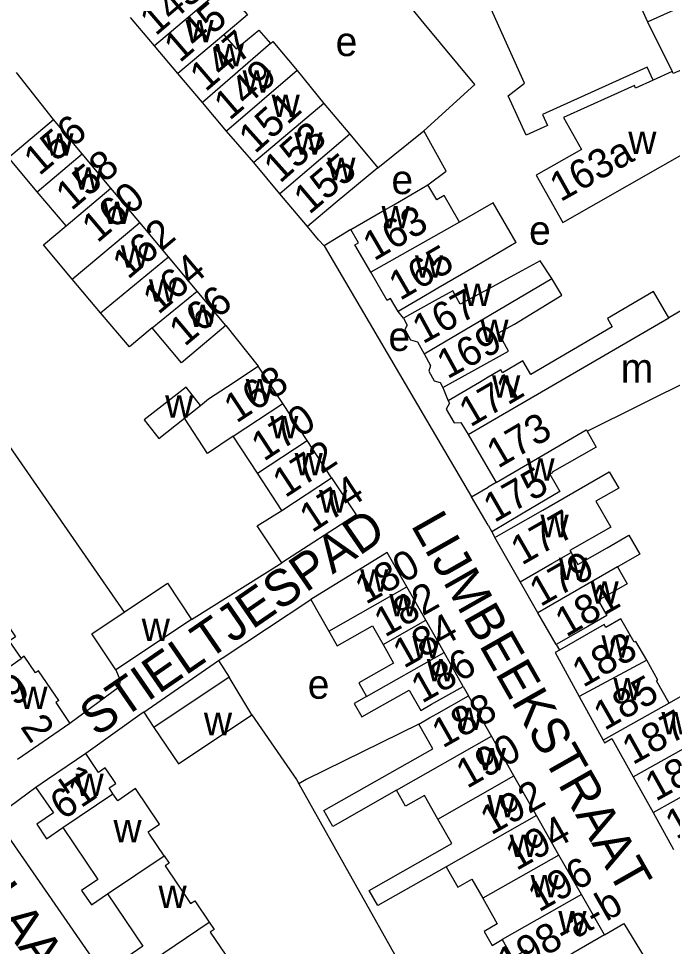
# Model space of a CAD drawing. Extents: x 159902 to 161769, y 383692 to 384875.
# Drawn here: x 160435.6 to 160525.3, y 384277.1 to 384404.5 of the extents above; entities that cross this region are included whole.
import ezdxf

# ---------------------------------------------------------------- set-up
doc = ezdxf.new("R2010")
doc.units = 0
for name, color, linetype in [('BLT_Basislijn', 7, 'Continuous'), ('BLT_Bebouwing', 7, 'Continuous'), ('BLT_Centroide', 7, 'Continuous'), ('BLT_Huisnummer', 7, 'Continuous'), ('BLT_Huisnummer_ tussenligend', 7, 'Continuous'), ('BLT_Huisnummer_reeks', 7, 'Continuous'), ('BLT_Onderverdeling_panden', 7, 'Continuous'), ('BLT_Straatnaam', 7, 'Continuous')]:
    doc.layers.add(name, color=color, linetype=linetype)

msp = doc.modelspace()

# ---------------------------------------------------------------- linework, layer by layer
at = {"layer": 'BLT_Basislijn'}
for p, q in [((160440.36, 384390.62), (160435.26, 384397.06)), ((160484.85, 384383.96), (160491.17, 384389.04)), ((160481.17, 384375.49), (160477.49, 384373.26)), ((160477.49, 384373.26), (160497.72, 384338.79)), ((160415.44, 384373.03), (160450.04, 384322.96)), ((160488.37, 384363.35), (160487.64, 384364.26)), ((160464.02, 384362.35), (160468.46, 384356.74)), ((160493.79, 384353.84), (160494.5, 384351.99)), ((160500.52, 384334.03), (160500.92, 384333.22)), ((160459.31, 384321.98), (160471.68, 384329.73)), ((160452.74, 384309.26), (160463.01, 384316.34)), ((160463.01, 384316.34), (160464.49, 384314.07)), ((160496.59, 384312.79), (160497.31, 384311.49)), ((160452.74, 384309.26), (160454.15, 384307.16))]:
    msp.add_line(p, q, dxfattribs=at)
for points in [[(160491.25, 384403.78), (160481.76, 384415.42), (160480.46, 384416.68), (160479.73, 384417.05), (160473.36, 384417.19), (160471.38, 384418.38), (160465.25, 384423.15), (160460.59, 384427.48)], [(160491.17, 384389.04), (160498.17, 384395.4), (160491.25, 384403.78)], [(160491.75, 384381.65), (160494.27, 384383.51), (160491.17, 384389.04)], [(160477.49, 384373.26), (160476.74, 384374.11), (160475.22, 384375.91)], [(160463.01, 384316.34), (160463.52, 384316.68), (160475.68, 384324.74)], [(160448.92, 384315.05), (160449.48, 384313.73), (160449.41, 384312.71), (160442.62, 384307.71)], [(160452.74, 384309.26), (160452.54, 384309.12), (160444.8, 384303.56)], [(160467.58, 384308.87), (160473.72, 384300), (160474.04, 384299.43)], [(160490.49, 384307.61), (160475.05, 384300), (160474.04, 384299.43)], [(160474.04, 384299.43), (160495.78, 384260.7), (160498.73, 384251.22), (160500, 384249.27), (160516.04, 384225.27), (160524.9, 384211.57)], [(160437.92, 384298.9), (160433.19, 384295.39), (160432.67, 384294.41), (160432.8, 384294.03), (160500, 384196.88), (160500.95, 384195.48)], [(160515.97, 384278.66), (160518.65, 384280.22), (160527, 384266.52), (160535.29, 384253.64), (160538.73, 384247.82), (160538.73, 384247.5), (160546.53, 384236.66)]]:
    msp.add_lwpolyline(points, dxfattribs=at)
at = {"layer": 'BLT_Bebouwing'}
for p, q in [((160454.22, 384400.73), (160450.94, 384404.6)), ((160457.44, 384396.91), (160454.22, 384400.73)), ((160473.8, 384397.35), (160477.44, 384392.81)), ((160460.8, 384392.94), (160457.44, 384396.91)), ((160464.12, 384389.03), (160460.8, 384392.94)), ((160477.44, 384392.81), (160481.04, 384388.62)), ((160444.3, 384385.91), (160440.36, 384390.62)), ((160467.83, 384384.69), (160464.12, 384389.03)), ((160510.26, 384376.49), (160532.48, 384389.13)), ((160448.24, 384381.2), (160444.3, 384385.91)), ((160471.41, 384380.41), (160467.83, 384384.69)), ((160506.59, 384382.95), (160510.26, 384376.49)), ((160452.19, 384376.48), (160448.24, 384381.2)), ((160442.09, 384376), (160438.13, 384380.7)), ((160475.22, 384375.91), (160471.41, 384380.41)), ((160456.13, 384371.77), (160452.19, 384376.48)), ((160460.08, 384367.06), (160456.13, 384371.77)), ((160464.02, 384362.35), (160460.08, 384367.06)), ((160513.59, 384347.81), (160535.78, 384358.86)), ((160471.82, 384351.64), (160468.46, 384356.74)), ((160501.74, 384356.25), (160500, 384355.22)), ((160475.17, 384346.54), (160471.82, 384351.64)), ((160468.36, 384342.06), (160465, 384347.16)), ((160478.53, 384341.43), (160475.17, 384346.54)), ((160497.25, 384347.35), (160500, 384342.66)), ((160500, 384342.66), (160501.1, 384340.78)), ((160471.71, 384336.95), (160468.36, 384342.06)), ((160497.72, 384338.79), (160500, 384340.13)), ((160501.1, 384340.78), (160500, 384340.13)), ((160500, 384334.91), (160497.72, 384338.79)), ((160500, 384334.91), (160500.52, 384334.03)), ((160504.41, 384327.15), (160500.92, 384333.22)), ((160491.45, 384321.87), (160488.86, 384326.45)), ((160506.84, 384322.91), (160504.41, 384327.15)), ((160509.36, 384318.53), (160506.84, 384322.91)), ((160459.31, 384321.98), (160448.92, 384315.05)), ((160493.96, 384317.44), (160491.45, 384321.87)), ((160509.36, 384318.53), (160509.79, 384317.78)), ((160496.59, 384312.79), (160493.96, 384317.44)), ((160464.49, 384314.07), (160454.15, 384307.16)), ((160467.58, 384308.87), (160464.49, 384314.07)), ((160527.57, 384312.02), (160524.87, 384310.48)), ((160500.46, 384305.94), (160497.31, 384311.49)), ((160442.62, 384307.71), (160435.4, 384302.73)), ((160503.55, 384300.5), (160500.46, 384305.94)), ((160516.99, 384305.63), (160519.91, 384300.39)), ((160506.64, 384295.07), (160503.55, 384300.5)), ((160519.91, 384300.39), (160522.64, 384295.48)), ((160522.64, 384295.48), (160525.47, 384290.4)), ((160509.73, 384289.64), (160506.64, 384295.07)), ((160512.81, 384284.2), (160509.73, 384289.64)), ((160515.97, 384278.66), (160512.81, 384284.2))]:
    msp.add_line(p, q, dxfattribs=at)
for points in [[(160522.66, 384396.02), (160521.85, 384397.81), (160507.48, 384391.32), (160508.17, 384389.79), (160505.22, 384388.46), (160502.78, 384393.87), (160505.02, 384395.59), (160500.24, 384406.16), (160503.67, 384407.71), (160501.51, 384412.5), (160498.31, 384419.6)], [(160515.89, 384417.33), (160521.9, 384404.02)], [(160521.9, 384404.02), (160544.69, 384414.31)], [(160463.68, 384408.73), (160465.34, 384406.84), (160466.97, 384404.98), (160463.75, 384402.26)], [(160463.75, 384402.26), (160465.43, 384400.33), (160468.56, 384402.89), (160470.15, 384401.04)], [(160470.15, 384401.04), (160470.45, 384401.3), (160473.8, 384397.35)], [(160522.66, 384396.02), (160520.24, 384394.92), (160520.09, 384395.26), (160510.36, 384390.88)], [(160438.13, 384380.7), (160434.17, 384385.4), (160436.54, 384387.4), (160440.36, 384390.62)], [(160510.36, 384390.88), (160512.81, 384386.49), (160506.59, 384382.95)], [(160481.04, 384388.62), (160484.85, 384383.96)], [(160484.85, 384383.96), (160479.03, 384379.15), (160475.22, 384375.91)], [(160481.17, 384375.49), (160485.49, 384378.01), (160487.05, 384378.92), (160491.75, 384381.65)], [(160496.07, 384376.53), (160493.99, 384380.17), (160492.96, 384379.57), (160491.75, 384381.65)], [(160503.87, 384373.71), (160500.69, 384379.18), (160496.07, 384376.53)], [(160442.93, 384368.71), (160438.98, 384373.39), (160442.09, 384376)], [(160483.9, 384369.65), (160481.71, 384373.4), (160482.22, 384373.69), (160481.17, 384375.49)], [(160503.87, 384373.71), (160498.41, 384370.53), (160493.1, 384367.44), (160491.96, 384366.78), (160487.64, 384364.26)], [(160508.75, 384368.77), (160507.14, 384371.22), (160504.61, 384369.85), (160500, 384367.33)], [(160487.64, 384364.26), (160486.6, 384366.05), (160486.15, 384365.78), (160483.9, 384369.65)], [(160446.82, 384364.09), (160442.93, 384368.71)], [(160502.8, 384358.8), (160501.43, 384361.31), (160503.64, 384362.52), (160510.11, 384366.49), (160508.75, 384368.77)], [(160533.05, 384368.2), (160524.8, 384363.39)], [(160500, 384367.33), (160496.17, 384365.24), (160495.17, 384367.07), (160492.76, 384365.75), (160488.37, 384363.35)], [(160524.8, 384363.39), (160522.68, 384366.99), (160516.39, 384363.29), (160517.05, 384362.17), (160505.86, 384355.62), (160504.76, 384357.48), (160501.98, 384355.85), (160501.74, 384356.25)], [(160453.9, 384362), (160450.79, 384359.39), (160446.82, 384364.09)], [(160488.37, 384363.35), (160488.91, 384362.36), (160488.57, 384361.8), (160489.36, 384360.36), (160490.32, 384360.08), (160491.21, 384358.46)], [(160464.02, 384362.35), (160460.2, 384359.12), (160457.93, 384357.22), (160453.9, 384362)], [(160491.21, 384358.46), (160492.09, 384356.84), (160491.86, 384356.06), (160492.58, 384354.75), (160493.43, 384354.5), (160493.79, 384353.84)], [(160493.79, 384353.84), (160498.18, 384356.24), (160502.8, 384358.8)], [(160460.53, 384351.37), (160461.65, 384352.26), (160464.26, 384353.98), (160468.46, 384356.74)], [(160500, 384355.22), (160498.82, 384354.53), (160494.5, 384351.99)], [(160460.53, 384351.37), (160458.58, 384353.85), (160452.8, 384349.38), (160454.82, 384346.83), (160458.33, 384349.6)], [(160494.5, 384351.99), (160494.7, 384351.66), (160494.25, 384350.87), (160495.36, 384348.99), (160496.27, 384349), (160497.25, 384347.35)], [(160465, 384347.16), (160461.5, 384344.78), (160458.33, 384349.6)], [(160513.59, 384347.81), (160514.85, 384345.65), (160508.78, 384342.21), (160508.86, 384342.1), (160508.49, 384341.92), (160509.87, 384339.54), (160504.83, 384336.56), (160500.52, 384334.03)], [(160478.53, 384341.43), (160481.89, 384336.33), (160471.68, 384329.73)], [(160500.92, 384333.22), (160503.17, 384334.51), (160507.51, 384337), (160516.64, 384342.24), (160517.93, 384340), (160514.77, 384338.22), (160516.83, 384334.65), (160511.24, 384331.44), (160511.4, 384331.16)], [(160471.68, 384329.73), (160468.33, 384334.81), (160471.71, 384336.95)], [(160511.4, 384331.16), (160512.34, 384329.53), (160516.36, 384331.83), (160519.32, 384333.53), (160520.81, 384330.94), (160517.86, 384329.23), (160517.77, 384329.18)], [(160488.86, 384326.45), (160486.17, 384331.19), (160475.68, 384324.74)], [(160517.77, 384329.18), (160518.54, 384327.84), (160519.09, 384326.87), (160515.11, 384324.59), (160516.3, 384322.51), (160513.7, 384321.02), (160509.36, 384318.53)], [(160430.15, 384326.01), (160431.87, 384323.49), (160432.38, 384323.68), (160435.15, 384319.61), (160434.28, 384319.02), (160435.92, 384316.61)], [(160450.04, 384322.96), (160456.01, 384326.94), (160459.31, 384321.98)], [(160475.68, 384324.74), (160478.15, 384320.38)], [(160448.92, 384315.05), (160445.62, 384320.01), (160450.04, 384322.96)], [(160478.15, 384320.38), (160479.29, 384318.37), (160484.12, 384321.11), (160485.58, 384318.54)], [(160521.77, 384316.37), (160520.27, 384318.97), (160520.07, 384318.85), (160518.23, 384322.05), (160516.17, 384320.86), (160515.92, 384321.3), (160509.79, 384317.78)], [(160485.58, 384318.54), (160487.03, 384315.96), (160482.27, 384313.27), (160483.33, 384311.41)], [(160509.79, 384317.78), (160509.19, 384317.44), (160512.51, 384311.39)], [(160441.08, 384310.83), (160438.31, 384314.91), (160437.9, 384314.64), (160436.35, 384316.92), (160435.92, 384316.61)], [(160524.87, 384310.48), (160523.11, 384313.54), (160523.32, 384313.66), (160521.77, 384316.37)], [(160483.33, 384311.41), (160481.62, 384310.45), (160482.68, 384308.59), (160484.38, 384309.55), (160489.19, 384312.28), (160490.77, 384309.49), (160492.24, 384310.33), (160496.59, 384312.79)], [(160441.08, 384310.83), (160440.68, 384310.56), (160442.62, 384307.71)], [(160490.49, 384307.61), (160491.96, 384308.45), (160492.97, 384309.02), (160497.31, 384311.49)], [(160512.51, 384311.39), (160515.8, 384305.39)], [(160454.15, 384307.16), (160457.51, 384302.14), (160467.58, 384308.87)], [(160487.45, 384298.54), (160478.7, 384293.57), (160477.47, 384295.73), (160492.41, 384304.22), (160490.49, 384307.61)], [(160515.8, 384305.39), (160515.99, 384305.05), (160516.99, 384305.63)], [(160444.8, 384303.56), (160439.55, 384300), (160437.92, 384298.9)], [(160448.52, 384298.05), (160448, 384298.84), (160448.91, 384299.45), (160448.54, 384300), (160447.46, 384301.59), (160446.55, 384300.97), (160444.8, 384303.56)], [(160437.92, 384298.9), (160440.35, 384295.42), (160438.05, 384293.87), (160439.39, 384291.88), (160441.64, 384293.4)], [(160455.54, 384289.53), (160453.55, 384292.48), (160453.33, 384292.82), (160454.89, 384293.87), (160451.59, 384298.77), (160449.19, 384297.06), (160448.52, 384298.05)], [(160493.11, 384294.57), (160491.26, 384297.82), (160488.69, 384296.36), (160487.45, 384298.54)], [(160494.24, 384288.02), (160484.85, 384282.69), (160483.67, 384284.77), (160495.01, 384291.21), (160493.11, 384294.57)], [(160441.64, 384293.4), (160446.46, 384286.27), (160444.22, 384284.76), (160445.56, 384282.78), (160447.79, 384284.29)], [(160455.54, 384289.53), (160456.23, 384288.52), (160455.68, 384288.15), (160459.17, 384282.98), (160459.75, 384283.37), (160461.74, 384280.43)], [(160494.24, 384288.02), (160495.83, 384285.21), (160497.79, 384286.32), (160499.27, 384283.7)], [(160447.79, 384284.29), (160452.63, 384277.12), (160450.43, 384275.63), (160451.76, 384273.68), (160453.96, 384275.17)], [(160499.27, 384283.7), (160501.27, 384280.18), (160499.46, 384279.16), (160500.55, 384277.24), (160501.93, 384278.02)], [(160461.74, 384280.43), (160462.42, 384279.43), (160461.86, 384279.05), (160465.36, 384273.86), (160465.91, 384274.24), (160467.86, 384271.35)], [(160501.93, 384278.02), (160503.35, 384275.54), (160505.23, 384276.61), (160506.97, 384273.54), (160509.14, 384274.79)], [(160515.97, 384278.66), (160511.62, 384276.18), (160509.14, 384274.79)]]:
    msp.add_lwpolyline(points, dxfattribs=at)
at = {"layer": 'BLT_Onderverdeling_panden'}
for p, q in [((160463.68, 384408.73), (160454.22, 384400.73)), ((160521.9, 384404.02), (160525.26, 384397.19)), ((160463.75, 384402.26), (160457.44, 384396.91)), ((160470.15, 384401.04), (160460.8, 384392.94)), ((160473.8, 384397.35), (160464.12, 384389.03)), ((160477.44, 384392.81), (160467.83, 384384.69)), ((160481.04, 384388.62), (160471.41, 384380.41)), ((160438.13, 384380.7), (160444.3, 384385.91)), ((160442.09, 384376), (160448.24, 384381.2)), ((160442.93, 384368.71), (160452.19, 384376.48)), ((160496.07, 384376.53), (160483.9, 384369.65)), ((160446.82, 384364.09), (160456.13, 384371.77)), ((160491.21, 384358.46), (160508.75, 384368.77)), ((160453.9, 384362), (160460.08, 384367.06)), ((160500, 384348.96), (160524.8, 384363.39)), ((160465, 384347.16), (160471.82, 384351.64)), ((160497.25, 384347.35), (160500, 384348.96)), ((160501.1, 384340.78), (160513.45, 384348.02)), ((160513.45, 384348.02), (160513.59, 384347.81)), ((160468.36, 384342.06), (160475.17, 384346.54)), ((160471.71, 384336.95), (160478.53, 384341.43)), ((160517.77, 384329.18), (160506.84, 384322.91)), ((160478.15, 384320.38), (160488.86, 384326.45)), ((160485.58, 384318.54), (160491.45, 384321.87)), ((160483.33, 384311.41), (160493.96, 384317.44)), ((160429.15, 384311.88), (160435.92, 384316.61)), ((160521.77, 384316.37), (160512.51, 384311.39)), ((160524.87, 384310.48), (160515.8, 384305.39)), ((160487.45, 384298.54), (160500.46, 384305.94)), ((160519.91, 384300.39), (160528.01, 384304.89)), ((160522.64, 384295.48), (160530.79, 384300.01)), ((160441.64, 384293.4), (160448.52, 384298.05)), ((160506.64, 384295.07), (160494.24, 384288.02)), ((160447.79, 384284.29), (160455.54, 384289.53)), ((160509.73, 384289.64), (160499.27, 384283.7)), ((160512.81, 384284.2), (160501.93, 384278.02)), ((160453.96, 384275.17), (160461.74, 384280.43))]:
    msp.add_line(p, q, dxfattribs=at)
for points in [[(160528.96, 384398.45), (160525.39, 384396.92), (160525.26, 384397.19)], [(160525.26, 384397.19), (160522.66, 384396.02)], [(160458.33, 384349.6), (160460.53, 384351.37)], [(160504.41, 384327.15), (160508.74, 384329.64), (160511.4, 384331.16)], [(160493.11, 384294.57), (160503.55, 384300.5)]]:
    msp.add_lwpolyline(points, dxfattribs=at)

# ---------------------------------------------------------------- texts
at = {"layer": 'BLT_Centroide'}
for s, p in [('w', (160458.47, 384401.21)), ('e', (160479.08, 384399.32)), ('w', (160462.61, 384397.91)), ('w', (160466.31, 384394.28)), ('w', (160470.29, 384390.94)), ('w', (160439.25, 384385.66)), ('w', (160473.41, 384385.78)), ('w', (160519.24, 384385.88)), ('w', (160477.93, 384382.28)), ('w', (160443.2, 384380.97)), ('e', (160486.74, 384380.37)), ('w', (160447.15, 384376.25)), ('w', (160485.38, 384375.66)), ('e', (160505.63, 384373.42)), ('w', (160449.58, 384370.28)), ('w', (160489.96, 384368.91)), ('w', (160453.45, 384365.59)), ('w', (160496.62, 384365)), ('w', (160458.91, 384362.12)), ('w', (160498.94, 384360.05)), ('e', (160486.33, 384358.84)), ('m', (160518.21, 384354.5)), ('w', (160500.55, 384352.41)), ('w', (160466.73, 384351.94)), ('w', (160455.68, 384349.69)), ('w', (160470.09, 384346.84)), ('w', (160473.45, 384341.75)), ('w', (160505.27, 384341.03)), ('w', (160476.8, 384336.66)), ('w', (160507.19, 384333.27)), ('w', (160509.71, 384327.38)), ('w', (160482.45, 384325.78)), ('w', (160514.06, 384324.14)), ('w', (160486.44, 384322.41)), ('w', (160452.47, 384319)), ('w', (160489.61, 384316.62)), ('w', (160515.56, 384316.72)), ('w', (160491.59, 384313.47)), ('e', (160475.25, 384311.09)), ('w', (160517.19, 384310.88)), ('w', (160435.67, 384309.67)), ('w', (160495.46, 384306.81)), ('w', (160461, 384306.09)), ('w', (160523.79, 384306.19)), ('w', (160498.59, 384301.28)), ('w', (160443.38, 384297.72)), ('w', (160499.87, 384294.81)), ('w', (160448.59, 384291.39)), ('w', (160502.95, 384289.38)), ('w', (160505.83, 384283.84)), ('w', (160454.77, 384282.36)), ('w', (160509.64, 384278.88))]:
    msp.add_text(s, height=4, dxfattribs=at).set_placement(p)
at = {"layer": 'BLT_Huisnummer'}
for s, rotation, p in [('143', 40.6576, (160454.38, 384401.99)), ('147', 40.6576, (160461.23, 384394.32)), ('151', 41.7929, (160468.01, 384385.81)), ('156', 40.1435, (160438.41, 384382.79)), ('163a', 29.262, (160509.93, 384379.24)), ('155', 40.3279, (160475.46, 384377.47)), ('160', 40.1446, (160446.38, 384373.57)), ('163', 30.1934, (160484.35, 384371.12)), ('166', 40.1401, (160458.36, 384359.35)), ('167', 28.6514, (160491.05, 384359.73)), ('168', 33.3276, (160465.46, 384348.84)), ('171', 30.4129, (160497.56, 384348.31)), ('175', 29.8515, (160500.86, 384335.2)), ('174', 33.3296, (160475.84, 384333.79)), ('180', 29.5439, (160483.22, 384323.96)), ('179', 29.8462, (160507.18, 384323.65)), ('184', 29.5439, (160488.43, 384315.18)), ('185', 29.7782, (160515.98, 384306.65)), ('188', 29.5385, (160493.77, 384304.23)), ('187', 29.0809, (160519.86, 384301.95)), ('192', 29.5995, (160500.42, 384292.3)), ('191', 29.7782, (160525.82, 384291.7)), ('196', 29.6055, (160506.97, 384281.72))]:
    msp.add_text(s, height=4, rotation=rotation, dxfattribs=at).set_placement(p)
at = {"layer": 'BLT_Huisnummer_ tussenligend'}
for s, rotation, p in [('145', 40.6576, (160457.69, 384398.3)), ('149', 40.6576, (160464.53, 384390.38)), ('153', 41.7929, (160471.44, 384381.75)), ('158', 40.1435, (160442.81, 384377.99)), ('162', 40.1446, (160450.58, 384368.56)), ('165', 30.1934, (160487.91, 384365.68)), ('164', 40.1446, (160454.75, 384363.74)), ('169', 28.6514, (160494.41, 384354.92)), ('170', 33.3276, (160469.22, 384343.6)), ('173', 30.4129, (160501.35, 384342.64)), ('172', 33.3276, (160472.15, 384338.59)), ('177', 29.8515, (160504.62, 384329.34)), ('182', 29.5439, (160485.84, 384319.46)), ('181', 29.8462, (160510.71, 384319.48)), ('183', 29.8462, (160513.04, 384312.56)), ('186', 29.5385, (160490.92, 384310.39)), ('190', 29.5995, (160497.1, 384298.69)), ('189', 29.0809, (160523.01, 384296.93)), ('194', 29.6055, (160503.89, 384287.41))]:
    msp.add_text(s, height=4, rotation=rotation, dxfattribs=at).set_placement(p)
at = {"layer": 'BLT_Huisnummer_reeks'}
for s, rotation, p in [('59', 34.9758, (160432.57, 384308.27)), ('2', 304.2686, (160435.72, 384307.24)), ('1', 304.0517, (160440.76, 384300.26)), ('61', 34.069, (160441.66, 384294.35)), ('198-a-b', 29.6056, (160502.76, 384272.81))]:
    msp.add_text(s, height=4, rotation=rotation, dxfattribs=at).set_placement(p)
at = {"layer": 'BLT_Straatnaam'}
for s, rotation, p in [('STIELTJESPAD', 34.5676, (160446.22, 384305.77)), ('LIJMBEEKSTRAAT', 299.609, (160489.33, 384334.93)), ('METIUSLAAN', 305.609, (160415.93, 384304.21))]:
    msp.add_text(s, height=5, rotation=rotation, dxfattribs=at).set_placement(p)

doc.saveas('drawing.dxf')
